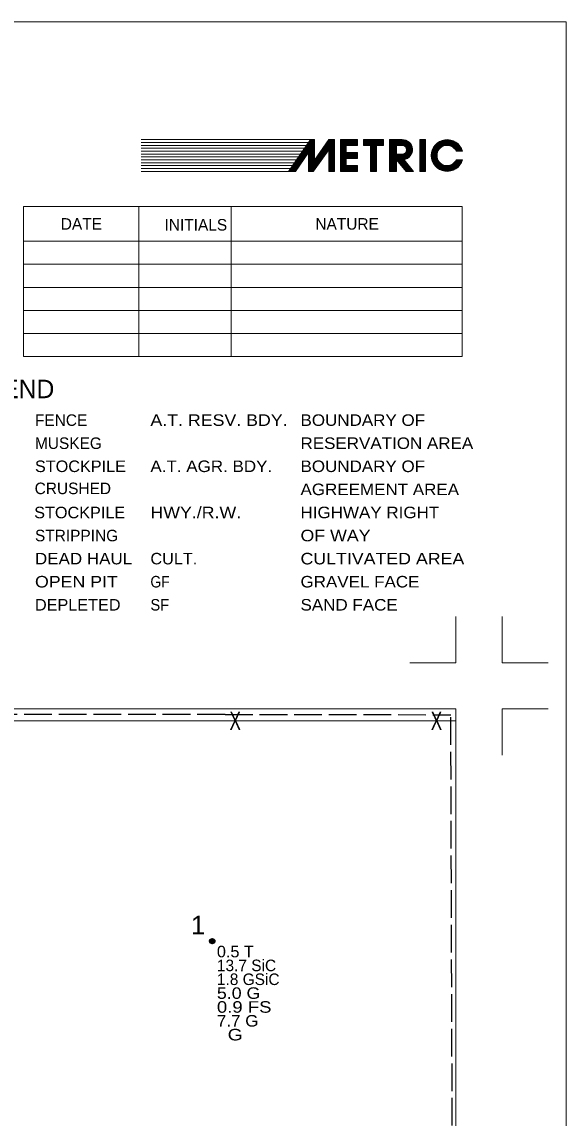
# Model space of a CAD drawing. Extents: x -577 to 499, y -450 to 700.
# Drawn here: x 214.3 to 450, y 225.1 to 700 of the extents above; entities that cross this region are included whole.
import ezdxf
from ezdxf.enums import TextEntityAlignment as Align

# ---------------------------------------------------------------- set-up
doc = ezdxf.new("R2010")
doc.units = 0
doc.header["$LTSCALE"] = 2
doc.linetypes.add('LONG_DASHED', pattern=[7.5, 6, -1.5])
for name, color, linetype, lineweight in [('1', 7, 'Continuous', 13), ('2', 7, 'Continuous', 35), ('3', 7, 'Continuous', 13)]:
    doc.layers.add(name, color=color, linetype=linetype, lineweight=lineweight)

msp = doc.modelspace()

# ---------------------------------------------------------------- linework, layer by layer
at = {"layer": '1'}
for p, q in [((339.376, 648.989), (265.976, 648.989)), ((338.501, 647.739), (265.976, 647.739)), ((337.626, 646.489), (265.976, 646.489)), ((329.726, 635.239), (339.376, 648.989)), ((340.976, 640.064), (347.226, 648.989)), ((349.726, 648.989), (347.226, 648.989)), ((349.726, 635.239), (349.726, 648.989)), ((354.726, 646.489), (354.726, 643.364)), ((362.226, 648.989), (362.226, 646.489)), ((362.226, 646.489), (365.351, 646.489)), ((367.851, 646.489), (370.976, 646.489)), ((379.026, 648.989), (373.476, 648.989)), ((376.601, 646.489), (379.151, 646.489)), ((376.601, 642.739), (376.601, 646.489)), ((336.751, 645.239), (265.976, 645.239)), ((335.876, 643.989), (265.976, 643.989)), ((335.001, 642.739), (265.976, 642.739)), ((334.126, 641.489), (265.976, 641.489)), ((332.776, 635.239), (338.476, 643.364)), ((338.476, 635.239), (338.476, 643.389)), ((340.676, 635.264), (347.226, 644.614)), ((347.226, 635.239), (347.226, 644.614)), ((376.601, 642.739), (379.151, 642.739)), ((402.426, 643.989), (405.076, 643.989)), ((333.251, 640.239), (265.976, 640.239)), ((332.376, 638.989), (265.976, 638.989)), ((331.501, 637.739), (265.976, 637.739)), ((330.626, 636.489), (265.976, 636.489)), ((354.726, 640.864), (354.726, 637.739)), ((376.601, 640.239), (380.726, 635.239)), ((376.601, 635.239), (376.601, 640.239)), ((379.801, 640.289), (383.951, 635.239)), ((402.426, 640.239), (405.101, 640.239)), ((329.726, 635.239), (265.976, 635.239)), ((329.726, 635.239), (332.776, 635.239)), ((338.476, 635.239), (340.676, 635.239)), ((349.726, 635.239), (347.226, 635.239)), ((352.226, 635.239), (359.726, 635.239)), ((380.726, 635.239), (383.951, 635.239)), ((404.983, 619.973), (214.983, 619.973)), ((214.983, 619.973), (214.983, 554.973)), ((264.983, 619.973), (264.983, 554.973)), ((304.983, 619.973), (304.983, 554.973)), ((404.983, 554.973), (404.983, 619.973)), ((214.983, 604.973), (404.983, 604.973)), ((214.983, 594.973), (404.983, 594.973)), ((214.983, 584.973), (404.983, 584.973)), ((214.983, 574.973), (404.983, 574.973)), ((214.983, 564.973), (404.983, 564.973)), ((214.983, 554.973), (404.983, 554.973)), ((402.281, 422.339), (402.281, 442.339)), ((422.281, 422.339), (422.281, 442.339)), ((402.281, 422.339), (382.281, 422.339)), ((422.281, 422.339), (442.281, 422.339)), ((422.281, 402.339), (442.281, 402.339)), ((422.281, 402.339), (422.281, 382.339))]:
    msp.add_line(p, q, dxfattribs=at)
for points in [[(449.983, -450.027), (449.983, 399.973), (449.983, 699.973), (-450.017, 699.973), (-450.017, 49.973), (-450.017, -450.027)], [(329.901, 635.339), (339.401, 648.889), (340.901, 648.889), (340.901, 639.839), (347.251, 648.839), (349.626, 648.889), (349.676, 635.339), (347.351, 635.314), (347.301, 644.789), (340.576, 635.339), (338.576, 635.314), (338.576, 643.539), (332.701, 635.339), (330.076, 635.314), (339.501, 648.739), (340.801, 648.739), (340.776, 639.664), (347.276, 648.664), (349.526, 648.739), (349.651, 635.564), (347.501, 635.464), (347.426, 644.989), (340.526, 635.489), (338.726, 635.439), (338.676, 643.764), (332.651, 635.464), (330.301, 635.439), (339.576, 648.539), (340.651, 648.564), (340.651, 639.489), (347.351, 648.489), (349.301, 648.564), (349.476, 635.739), (347.726, 635.639), (347.626, 645.314), (340.451, 635.714), (338.926, 635.639), (338.876, 644.139), (332.501, 635.689), (330.701, 635.639)], [(330.701, 635.639), (339.651, 648.239), (340.326, 648.264), (340.476, 639.239), (347.526, 648.239), (349.126, 648.289), (349.226, 635.939), (348.001, 635.939), (347.851, 645.664), (340.326, 635.989), (339.151, 635.864), (339.126, 644.464), (332.401, 635.939), (331.076, 635.839), (339.651, 647.914), (340.151, 647.914), (340.251, 638.889), (347.601, 647.964), (348.926, 648.014), (349.026, 636.164), (348.251, 636.139), (348.051, 646.014), (340.226, 636.239), (339.351, 636.089), (339.326, 644.789), (332.226, 636.164), (331.476, 636.064), (339.701, 647.664), (339.926, 647.689), (340.126, 638.764), (347.751, 647.839), (348.701, 647.739), (348.826, 636.364), (348.476, 636.364), (348.176, 646.314), (340.126, 636.464), (339.551, 636.339), (339.426, 645.114), (332.201, 636.339), (331.851, 636.289)], [(331.851, 636.289), (339.701, 647.264), (339.926, 638.564), (347.826, 647.614), (348.451, 647.589), (348.701, 636.589), (348.251, 646.639), (340.126, 636.689), (339.726, 636.589), (339.576, 645.539), (332.301, 636.639), (339.526, 646.714), (339.576, 645.814), (335.101, 640.239), (339.401, 646.164), (339.401, 645.914), (338.176, 644.289)], [(340.976, 640.039), (340.976, 648.989), (339.376, 648.989)], [(339.901, 638.414), (339.926, 636.839), (348.276, 646.889), (348.326, 647.439), (347.951, 647.439), (340.126, 638.539), (340.151, 637.314), (348.176, 647.064), (348.051, 647.214), (340.326, 638.539), (340.401, 637.839), (347.851, 646.839), (340.501, 638.639), (340.526, 638.389), (344.426, 642.914)], [(352.226, 635.239), (352.226, 648.989), (359.726, 648.989)], [(352.376, 648.914), (359.651, 648.864), (359.676, 646.614), (354.626, 646.589), (354.626, 643.289), (359.651, 643.289), (359.651, 640.989), (354.651, 640.939), (354.626, 637.614), (359.676, 637.639), (359.651, 635.339), (352.351, 635.314), (352.376, 648.789), (359.551, 648.739), (359.551, 646.764), (354.501, 646.714), (354.501, 643.214), (359.551, 643.164), (359.551, 641.114), (354.551, 641.064), (354.526, 637.439), (359.551, 637.514), (359.501, 635.439), (352.501, 635.439), (352.576, 648.639), (359.401, 648.564), (359.426, 646.914), (354.376, 646.839), (354.351, 643.064), (359.426, 643.039), (359.376, 641.289), (354.401, 641.239), (354.376, 637.239), (359.401, 637.339), (359.376, 635.589), (352.701, 635.614), (352.726, 648.439), (359.226, 648.414), (359.251, 647.064), (354.251, 647.039)], [(354.251, 647.039), (354.176, 642.864), (359.251, 642.864), (359.176, 641.439), (354.251, 641.389), (354.201, 637.064), (359.201, 637.114), (359.176, 635.739), (352.926, 635.814), (352.976, 648.214), (359.026, 648.239), (359.076, 647.289), (354.076, 647.214), (354.001, 642.689), (359.051, 642.664), (359.026, 641.639), (354.076, 641.564), (354.026, 636.864), (359.051, 636.939), (359.026, 635.989), (353.126, 636.039), (353.226, 647.989), (358.801, 648.039), (358.826, 647.464), (353.926, 647.389), (353.851, 642.489), (358.876, 642.539), (358.801, 641.814), (353.951, 641.689), (353.851, 636.714), (358.901, 636.764), (358.901, 636.214), (353.351, 636.214), (353.476, 647.714), (358.601, 647.889), (358.626, 647.639), (353.776, 647.514), (353.751, 642.364), (358.626, 642.389), (358.601, 642.014)], [(358.601, 642.014), (353.826, 641.864), (353.726, 636.564), (358.701, 636.639), (358.701, 636.389), (353.551, 636.439), (353.626, 641.989), (358.376, 642.164), (358.326, 642.289), (353.576, 642.264), (353.676, 647.564)], [(359.726, 648.989), (359.726, 646.489), (354.726, 646.489)], [(370.976, 646.489), (370.976, 648.989), (362.226, 648.989)], [(362.351, 648.864), (370.851, 648.889), (370.851, 646.639), (367.701, 646.639), (367.751, 635.414), (365.451, 635.314), (365.451, 646.564), (362.351, 646.589), (362.351, 648.764), (370.801, 648.789), (370.726, 646.789), (367.601, 646.764), (367.676, 635.539), (365.576, 635.414), (365.626, 646.739), (362.476, 646.739), (362.476, 648.639), (370.626, 648.639), (370.576, 646.989), (367.426, 646.864), (367.526, 635.739), (365.751, 635.614), (365.776, 646.864), (362.701, 646.939), (362.726, 648.439), (370.451, 648.489), (370.376, 647.114), (367.276, 646.989), (367.376, 635.914), (365.901, 635.789), (365.951, 647.064), (362.901, 647.114), (362.901, 648.264), (370.201, 648.289), (370.201, 647.364), (367.076, 647.189), (367.226, 636.114), (366.126, 635.989), (366.101, 647.264), (363.101, 647.314)], [(363.101, 647.314), (363.151, 648.089), (369.976, 648.164), (369.926, 647.489), (366.876, 647.364), (367.026, 636.339), (366.351, 636.239), (366.276, 647.439), (363.326, 647.514), (363.401, 647.939), (369.751, 648.039), (369.701, 647.714), (366.726, 647.539), (366.851, 636.564), (366.476, 636.489), (366.426, 647.664), (363.701, 647.664), (363.751, 647.839), (369.451, 647.914), (369.426, 647.814), (366.601, 647.664), (366.626, 636.689)], [(367.851, 646.489), (367.851, 635.239), (365.351, 635.239), (365.351, 646.489)], [(373.476, 648.989), (373.476, 635.239), (376.601, 635.239)], [(373.601, 648.914), (378.976, 648.889), (380.101, 648.739), (381.101, 648.364), (381.826, 647.789), (382.451, 647.189), (382.901, 646.414), (383.301, 645.389), (383.301, 644.439), (383.126, 643.214), (382.651, 642.314), (381.926, 641.489), (381.051, 640.889), (380.401, 640.639), (379.651, 640.389), (380.026, 639.714), (380.576, 639.189), (383.701, 635.339), (380.801, 635.314), (376.501, 640.464), (376.526, 635.339), (373.551, 635.314), (373.551, 648.864), (379.026, 648.789), (380.076, 648.639), (380.926, 648.314), (382.276, 647.214), (383.151, 645.364), (383.026, 643.314), (382.601, 642.464), (381.901, 641.614), (381.051, 640.989), (379.576, 640.464), (383.501, 635.414), (380.951, 635.439), (376.351, 640.739), (376.401, 635.489), (373.701, 635.439), (373.701, 648.739), (379.151, 648.664), (380.076, 648.489), (380.851, 648.189), (382.126, 647.139), (383.026, 645.389), (382.951, 643.539), (382.501, 642.564), (381.901, 641.739), (381.051, 641.114), (379.401, 640.614), (383.201, 635.564), (381.001, 635.564), (376.226, 640.889), (376.276, 635.614), (373.826, 635.539), (373.826, 648.614), (379.126, 648.489), (380.676, 648.089), (382.026, 647.139), (382.876, 645.439), (382.801, 643.664), (382.401, 642.664), (381.801, 641.889), (380.951, 641.189), (379.226, 640.764), (382.901, 635.689), (381.101, 635.689), (376.051, 641.064), (376.126, 635.789), (373.976, 635.689), (373.976, 648.439), (379.101, 648.364), (380.551, 647.989), (381.851, 647.089), (382.776, 645.439), (382.701, 643.764), (382.326, 642.889), (381.726, 642.064), (380.901, 641.339), (379.026, 640.939), (382.601, 635.789), (381.126, 635.814), (375.876, 641.239), (375.976, 635.939), (374.126, 635.864), (374.126, 648.239), (379.026, 648.239), (380.251, 647.914), (381.676, 647.014), (382.576, 645.414), (382.601, 643.914), (382.276, 642.989), (381.651, 642.214), (380.826, 641.514), (378.851, 641.064), (382.351, 635.939), (381.176, 635.989), (375.776, 641.514), (375.826, 636.089), (374.251, 636.014), (374.276, 648.039), (378.976, 648.114)], [(378.976, 648.114), (379.026, 648.114), (380.201, 647.764), (381.526, 646.939), (382.401, 645.489), (382.401, 643.964), (382.076, 643.114), (380.826, 641.764), (378.601, 641.264), (382.001, 636.114), (381.351, 636.114), (375.676, 641.789), (375.676, 636.264), (374.376, 636.189), (374.451, 647.864), (378.926, 647.939), (380.176, 647.689), (381.351, 646.914), (382.151, 645.414), (382.201, 644.014), (381.901, 643.214), (380.726, 641.989), (378.401, 641.389), (381.676, 636.314), (381.501, 636.189), (375.526, 642.064), (375.476, 636.414), (374.551, 636.339), (374.651, 647.739), (379.976, 647.614), (381.151, 646.914), (382.001, 645.414), (382.051, 644.139), (381.726, 643.339), (380.651, 642.139), (378.226, 641.589), (381.401, 636.464), (375.401, 642.364), (375.376, 636.614), (374.676, 636.539), (374.901, 647.589), (379.826, 647.414), (380.851, 646.889), (381.801, 645.439), (381.901, 644.389), (381.576, 643.539), (380.576, 642.414), (378.051, 641.739), (380.676, 637.364), (375.376, 642.614), (375.226, 636.739), (374.851, 636.739), (375.076, 647.339), (379.601, 647.314), (380.676, 646.839), (381.626, 645.414), (381.726, 644.464), (381.376, 643.589), (380.501, 642.589), (377.826, 641.864), (380.026, 638.189), (375.251, 642.889), (375.076, 636.939), (374.926, 636.989), (375.226, 647.189), (379.526, 647.139), (380.551, 646.714), (381.401, 645.414), (381.551, 644.614), (380.376, 642.739), (377.726, 642.039), (379.276, 639.239), (375.351, 643.039), (375.426, 646.989), (379.476, 646.989), (380.526, 646.639), (381.251, 645.489), (381.326, 644.614), (380.276, 642.914), (377.551, 642.239), (378.601, 640.139), (375.576, 643.139), (375.676, 646.839), (379.451, 646.839), (380.476, 646.514), (381.101, 645.414), (381.051, 644.489), (380.876, 645.464), (380.501, 646.039), (380.151, 646.339), (379.476, 646.514), (378.751, 646.639), (377.601, 646.614), (376.476, 646.614), (376.501, 642.714), (378.626, 642.664), (377.376, 642.339), (378.126, 640.764), (375.726, 643.164), (375.876, 646.714), (379.451, 646.714)], [(376.026, 646.614), (375.901, 643.214), (377.551, 641.614), (377.251, 642.364), (377.776, 642.614), (376.826, 642.614), (377.201, 642.164)], [(376.151, 646.564), (376.051, 643.314), (376.376, 643.064), (376.351, 646.564), (376.251, 643.389)], [(379.451, 646.714), (379.401, 646.739), (380.451, 646.289)], [(386.776, 648.839), (388.951, 648.864), (389.001, 635.364), (386.701, 635.364), (386.676, 648.739), (388.851, 648.764), (388.876, 635.489), (386.826, 635.439), (386.801, 648.614), (388.776, 648.639), (388.776, 635.664), (386.976, 635.589), (386.926, 648.464), (388.626, 648.464), (388.601, 635.764), (387.126, 635.764), (387.101, 648.364), (388.501, 648.364), (388.451, 635.939), (387.301, 635.964), (387.301, 648.214), (388.401, 648.214), (388.301, 636.089), (387.426, 636.089), (387.476, 648.064), (388.251, 648.039), (388.151, 636.214), (387.576, 636.214), (387.676, 647.914), (388.126, 647.889), (388.001, 636.339), (387.776, 636.389), (387.826, 647.764), (387.976, 647.714), (387.901, 636.539)], [(404.901, 644.089), (404.451, 645.189), (403.851, 646.164), (403.151, 646.914), (402.301, 647.639), (401.151, 648.289), (400.126, 648.614), (398.801, 648.814), (397.351, 648.689), (395.876, 648.339), (394.601, 647.639), (393.601, 646.764), (392.776, 645.664), (392.176, 644.564), (391.801, 642.964), (391.801, 641.264), (392.176, 639.789), (392.726, 638.564), (393.351, 637.739), (394.101, 637.014), (394.976, 636.389), (395.901, 635.914), (397.126, 635.489), (398.726, 635.389), (400.151, 635.589), (401.301, 635.989), (402.326, 636.564), (403.326, 637.414), (404.001, 638.264), (404.426, 639.139), (404.801, 640.064), (402.526, 640.089), (401.776, 638.989), (400.776, 638.289), (399.801, 637.814), (398.476, 637.564), (397.026, 637.839), (396.126, 638.289), (395.276, 638.939), (394.551, 639.939), (394.076, 641.189), (394.051, 642.814), (394.276, 643.889), (394.901, 644.889), (395.601, 645.614), (396.476, 646.164), (397.376, 646.489), (398.426, 646.614), (399.526, 646.489), (400.426, 646.214), (401.176, 645.764), (401.801, 645.239), (402.301, 644.664), (402.576, 644.139), (404.726, 644.164), (404.251, 645.214), (403.651, 646.164), (402.276, 647.489), (401.126, 648.114), (399.351, 648.614), (397.876, 648.564), (396.551, 648.339), (395.226, 647.814), (394.351, 647.264), (393.451, 646.339), (392.676, 645.139), (392.176, 643.939), (391.976, 642.239), (392.076, 640.689), (392.576, 639.164), (393.476, 637.864), (394.526, 636.864), (395.701, 636.164), (397.201, 635.639), (398.626, 635.514), (400.251, 635.764), (401.276, 636.089), (402.301, 636.789), (403.176, 637.439), (403.726, 638.164), (404.376, 639.239), (404.551, 639.964), (402.626, 639.989), (402.076, 639.064), (400.751, 638.139), (399.826, 637.689), (398.526, 637.389), (396.976, 637.739), (395.601, 638.439), (394.651, 639.639), (394.076, 640.764), (393.876, 642.139), (394.151, 643.989), (394.726, 644.964), (395.826, 646.014), (397.051, 646.539), (398.351, 646.789), (399.826, 646.614), (401.026, 646.064), (401.701, 645.614), (402.226, 645.014)], [(402.226, 645.014), (402.301, 645.014), (402.676, 644.239), (404.476, 644.264), (404.026, 645.314), (402.876, 646.664), (401.901, 647.489), (400.851, 648.089), (399.251, 648.514), (396.976, 648.264), (395.201, 647.614), (394.051, 646.639), (393.151, 645.614), (392.526, 644.239), (392.176, 642.439), (392.326, 640.539), (392.676, 639.489), (392.951, 638.864), (393.701, 637.864), (394.851, 636.839), (397.101, 635.814), (398.651, 635.664), (401.026, 636.164), (403.076, 637.564), (403.901, 638.814), (404.326, 639.814), (403.476, 639.789), (402.726, 639.839), (402.201, 638.889), (400.776, 637.964), (399.526, 637.414), (398.251, 637.264), (396.651, 637.714), (395.476, 638.364), (394.451, 639.714), (393.901, 640.864), (393.701, 642.264), (393.976, 643.889), (394.651, 645.264), (395.701, 646.214), (397.376, 646.789), (398.851, 646.914), (400.251, 646.614), (401.626, 645.914), (402.426, 645.164), (402.801, 644.439), (404.226, 644.414), (403.426, 645.739), (402.676, 646.614), (401.826, 647.314), (400.851, 647.939), (399.276, 648.314), (397.051, 648.089), (395.226, 647.364), (393.976, 646.314), (393.201, 645.414), (392.651, 643.839), (392.426, 642.514), (392.451, 641.239), (392.651, 640.089), (393.101, 639.039), (393.651, 638.239), (394.376, 637.564), (395.226, 636.839), (396.351, 636.314), (397.451, 635.914), (398.701, 635.839), (400.826, 636.364), (402.976, 637.639), (403.801, 638.964), (404.026, 639.714), (402.851, 639.664), (402.326, 638.814), (401.226, 638.164), (399.651, 637.239), (398.226, 637.114), (397.101, 637.389), (395.976, 637.889), (394.801, 638.989), (394.101, 640.014), (393.601, 641.664), (393.676, 643.264), (394.101, 644.689), (395.376, 646.214), (396.876, 646.764), (398.751, 647.064), (400.326, 646.764), (401.751, 646.089), (402.651, 645.189), (402.951, 644.539), (403.876, 644.614), (403.051, 645.989), (402.201, 646.789), (400.851, 647.739), (399.376, 648.189), (397.151, 647.889), (395.451, 647.239), (394.076, 646.164), (393.251, 645.039), (392.701, 643.014), (392.651, 641.564)], [(392.651, 641.564), (392.676, 641.614), (392.951, 639.914), (393.451, 638.964), (394.051, 638.214), (394.926, 637.289), (395.951, 636.764), (396.601, 636.389), (397.801, 636.039), (398.776, 635.989), (400.726, 636.464), (402.951, 637.739), (403.651, 639.064), (403.726, 639.564), (403.026, 639.539), (402.576, 638.814), (399.876, 637.114), (398.026, 637.014), (396.051, 637.664), (394.476, 639.139), (393.526, 641.439), (393.651, 643.889), (394.476, 645.514), (395.726, 646.539), (397.351, 646.989), (398.701, 647.239), (400.476, 646.939), (401.751, 646.339), (402.526, 645.664), (402.851, 645.114), (403.076, 644.739), (403.551, 644.789), (402.926, 645.989), (401.801, 646.914), (400.676, 647.639), (399.376, 648.039), (397.176, 647.789), (395.676, 647.164), (394.226, 646.139), (393.501, 645.039), (392.901, 643.314), (392.826, 641.639), (393.126, 639.989), (393.851, 638.689), (394.951, 637.514), (396.001, 636.989), (396.726, 636.564), (398.626, 636.139), (400.701, 636.614), (402.776, 637.864), (403.476, 639.064), (403.601, 639.464), (403.251, 639.389), (402.751, 638.739), (400.001, 637.014), (398.001, 636.889), (395.901, 637.564), (394.326, 639.064), (393.376, 641.464), (393.576, 643.939), (394.301, 645.589), (395.526, 646.689), (398.576, 647.339), (400.751, 647.089), (401.751, 646.489), (402.601, 645.914), (403.076, 645.039), (403.326, 644.914), (402.851, 645.939), (400.926, 647.289), (399.526, 647.889), (397.401, 647.714), (395.626, 647.039), (394.251, 646.039), (393.576, 644.889), (393.026, 643.239), (392.951, 641.714), (393.276, 640.314), (393.801, 639.139), (394.376, 638.339), (395.076, 637.639), (396.901, 636.764), (398.651, 636.314), (400.576, 636.789), (402.601, 637.914), (403.351, 639.139), (402.501, 638.339), (401.601, 637.789), (400.101, 636.864), (398.051, 636.764), (395.801, 637.439), (394.176, 639.064), (393.226, 641.539), (393.501, 644.014), (394.126, 645.639), (395.451, 646.739), (397.026, 647.189), (398.576, 647.489), (399.776, 647.389), (400.526, 647.289), (399.551, 647.639)], [(399.551, 647.639), (398.601, 647.639), (397.451, 647.489), (395.901, 647.064)], [(354.726, 640.864), (359.726, 640.864), (359.726, 643.364), (354.726, 643.364)], [(402.751, 638.439), (402.076, 637.814), (400.676, 637.089), (399.226, 636.639), (398.501, 636.639), (396.951, 636.914), (395.751, 637.364), (394.201, 638.764), (393.101, 641.589), (393.401, 643.964), (393.901, 645.289)], [(354.726, 637.739), (359.726, 637.739), (359.726, 635.239)], [(402.281, -402.333), (402.281, 402.339), (-402.391, 402.339)]]:
    msp.add_lwpolyline(points, dxfattribs=at)
msp.add_lwpolyline([(386.601, 635.239), (386.601, 648.989), (389.101, 648.989), (389.101, 635.239)], close=True, dxfattribs=at)
for centre, radius, start, end in [((379.076, 644.614), 4.375, 279.51602, 90.65478), ((379.051, 644.614), 1.875, 272.29061, 86.94712), ((398.476, 642.114), 6.875, 15.80251, 344.19749), ((398.476, 642.114), 4.375, 25.39292, 334.60708)]:
    msp.add_arc(centre, radius, start, end, dxfattribs=at)
at = {"layer": '2', "linetype": 'LONG_DASHED', "lineweight": 25}
for p in [(302.281, 400), (401.147, 86.828)]:
    msp.add_line(p, (400.063, 399.851), dxfattribs=at)
msp.add_lwpolyline([(302.281, 400), (-302.391, 400), (-302.391, 340.778)], dxfattribs=at)
at = {"layer": '2'}
msp.add_circle((296.775, 301.751), 1, dxfattribs=at)
msp.add_spline([(296.764, 302.638), (297.495, 302.234), (297.646, 301.386), (296.961, 300.858), (296.152, 301.088), (295.866, 301.846), (296.113, 302.408), (296.686, 302.576), (297.36, 302.082), (297.343, 301.341), (296.826, 301.082), (296.304, 301.251), (296.079, 301.897), (296.663, 302.363), (297.101, 301.829), (297.062, 301.346), (296.433, 301.481), (296.579, 302.116), (296.871, 301.565)], degree=3, dxfattribs=at)
at = {"layer": '3'}
msp.add_line((402.29, 397.182), (-112.541, 397.182), dxfattribs=at)

# ---------------------------------------------------------------- texts
at = {"layer": '1'}
for s, height, p in [('DATE', 5, (240.081, 609.973)), ('INITIALS', 5, (289.66, 609.584)), ('NATURE', 5, (355.16, 609.973)), ('LEGEND', 8, (206.378, 536.973))]:
    msp.add_text(s, height=height, dxfattribs=at).set_placement(p, align=Align.CENTER)
for s, p in [('FENCE', (219.983, 524.973)), ('MUSKEG', (219.983, 514.973)), ('CRUSHED', (219.856, 495.402)), ('STRIPPING', (219.983, 474.973))]:
    msp.add_text(s, height=5, dxfattribs=at).set_placement(p)
for s, width, p in [('A.T. RESV. BDY.', 1.15, (269.983, 524.973)), ('BOUNDARY OF', 1.1, (334.983, 524.973)), ('RESERVATION AREA', 1.1, (334.983, 514.973)), ('STOCKPILE', 1.05, (219.983, 504.973)), ('A.T. AGR. BDY.', 1.1, (269.983, 504.973)), ('BOUNDARY OF', 1.1, (334.983, 504.973)), ('AGREEMENT AREA', 1.1, (334.983, 494.973)), ('STOCKPILE', 1.05, (219.649, 484.941)), ('HWY./R.W.', 1.15, (269.983, 484.973)), ('HIGHWAY RIGHT', 1.1, (334.983, 484.973)), ('OF WAY', 1.15, (334.983, 474.973)), ('DEAD HAUL', 1.1, (219.983, 464.973)), ('CULT.', 1.05, (269.983, 464.973)), ('CULTIVATED AREA', 1.15, (334.983, 464.973)), ('OPEN PIT', 1.15, (219.983, 454.973)), ('GF', 0.9, (269.983, 454.973)), ('GRAVEL FACE', 1.1, (334.983, 454.973)), ('DEPLETED', 1.05, (219.983, 444.973)), ('SF', 0.95, (269.983, 444.973)), ('SAND FACE', 1.1, (334.983, 444.973))]:
    msp.add_text(s, height=5, dxfattribs=dict(at, width=width)).set_placement(p)
at = {"layer": '2', "width": 1.05}
msp.add_text('  1', height=8, dxfattribs=at).set_placement((293.775, 304.751), align=Align.RIGHT)
at = {"layer": '2'}
for s, width, p in [('0.5 T      ', 1.05, (298.775, 294.751)), ('5.0 G      ', 1.15, (298.775, 276.751)), ('0.9 FS     ', 1.2, (298.775, 270.751)), ('7.7 G      ', 1.1, (298.775, 264.751)), ('  G        ', 1.25, (298.775, 258.751))]:
    msp.add_text(s, height=5, dxfattribs=dict(at, width=width)).set_placement(p)
for s, p in [('13.7 SiC   ', (298.775, 288.751)), ('1.8 GSiC   ', (298.775, 282.751))]:
    msp.add_text(s, height=5, dxfattribs=at).set_placement(p)
at = {"layer": '3', "width": 0.7}
for p in [(306.689, 393.172), (393.86, 393.162)]:
    msp.add_text('X', height=8, dxfattribs=at).set_placement(p, align=Align.CENTER)

doc.saveas('drawing.dxf')
